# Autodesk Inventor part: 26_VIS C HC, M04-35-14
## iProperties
Created: 2002-07
Part Number: 26_VIS C HC, M04-35-14
Material: C35
Document SubType Name: Modélisation
Designer: FIEVET
Company: Lycée Joliot Curie
Control State: 0
Master: False
Checked Out: False
Shininess: 20.0
Length Units: 11269
Angle Units: 11279
Time Units: 11290
Mass Units: 11283
Length Display Precision: 3
Angle Display Precision: 2
Compacted: True
Density: 7.0
Volumn: 0.05448716042290158
Area: 1.0376231375495402
PropertySet Name: Model Information
Title: Vis CHC
Subject: NF EN ISO 4762
Author: FIEVET
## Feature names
1. Révolution1 [Revolution]
2. Chanfrein1 [Chamfer]
3. Extrusion1
